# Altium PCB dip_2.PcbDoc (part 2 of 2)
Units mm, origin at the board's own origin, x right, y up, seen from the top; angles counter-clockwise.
Board outline 62.5 x 72.5 mm, 2 copper layers (Top Layer, Bottom Layer); 36 components, 64 nets, 215 pads, 49 vias.
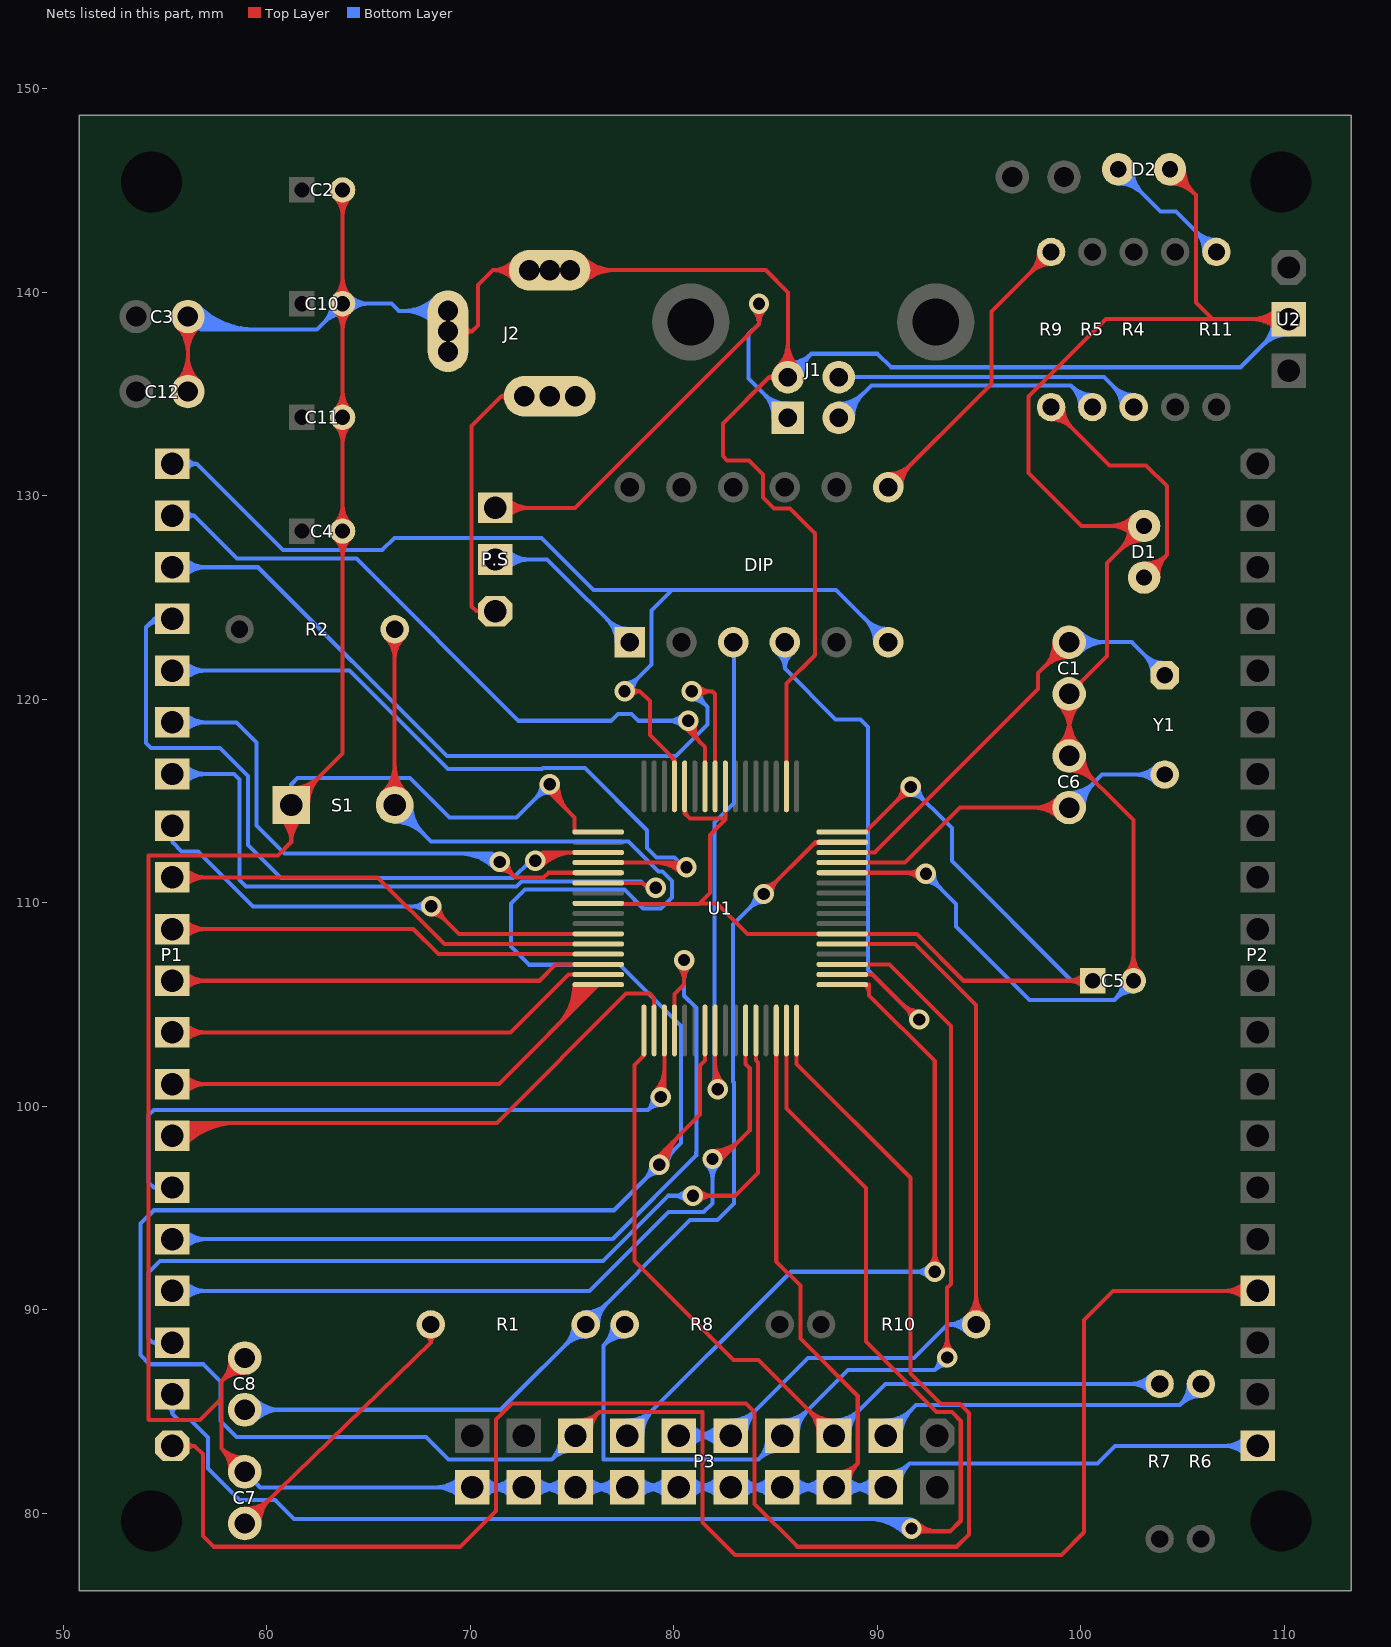
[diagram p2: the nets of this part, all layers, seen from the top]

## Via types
v1: diameter 1, hole 0.6, Top Layer to Bottom Layer, 49 vias

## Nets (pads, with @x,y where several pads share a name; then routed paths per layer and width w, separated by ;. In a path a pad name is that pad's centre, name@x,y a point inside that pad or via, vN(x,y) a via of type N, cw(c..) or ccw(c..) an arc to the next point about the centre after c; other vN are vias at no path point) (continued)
GND: C1.2 C2.2 C3.1 C4.2 C5.2 C6.2 C7.2 C8.2 C10.2 C11.2 C12.1 D1.2 D2.2 J1.4 J2.2 J2.2A J2.2B J2.3 J2.3A J2.3B P2.20 P3.4 P3.6 P3.8 P3.10 P3.12 P3.14 P3.16 P3.18 P3.20 S1.1 U1.2 U1.17 U1.46 U1.60 U2.2 | length 627.8
  Top Layer w0.2: C12.1@55.621,135.641 ccw(c54.384,136.878) 56.134,136.878 ccw(c57.884,136.878) C12.1@56.647,135.641 ; C3.1@55.621,138.298 cw(c54.384,137.061) 56.134,137.061 cw(c57.884,137.061) C3.1@56.647,138.298 ; C12.1@55.763,135.499 ccw(c54.867,136.395) 56.134,136.395 ccw(c57.401,136.395) C12.1@56.505,135.499 ; C3.1@55.763,138.44 cw(c54.867,137.544) 56.134,137.544 cw(c57.401,137.544) C3.1@56.505,138.44 ; C12.1@56.134,135.128 C3.1@56.134,138.811 ; C7.2@58.204,82.084 ccw(c56.767,82.167) 57.785,83.185 ; C8.2@58.204,87.588 cw(c56.767,87.505) 57.785,86.487 ; C7.2@58.404,82.072 ccw(c57.363,82.133) 58.1,82.87 ccw(c58.837,83.607) C7.2@58.898,82.566 ; C8.2@58.404,87.6 cw(c57.363,87.539) 58.1,86.802 cw(c58.837,86.065) C8.2@58.898,87.106 ; C7.2@58.886,82.766 cw(c58.803,84.203) 57.785,83.185 ; C8.2@58.886,86.906 ccw(c58.803,85.469) 57.785,86.487 ; C7.2@58.928,82.042 57.785,83.185 ; C8.2@58.928,87.63 57.785,86.487 ; S1.1@60.668,114.19 cw(c59.6,112.979) 61.214,112.979 ; S1.1@60.8,114.339 cw(c59.991,113.423) 61.214,113.423 cw(c62.437,113.423) S1.1@61.628,114.339 ; S1.1@60.933,114.489 cw(c60.382,113.866) 61.214,113.866 cw(c62.046,113.866) S1.1@61.495,114.489 ; S1.1@61.214,115.233 ccw(c61.214,116.259) 61.94,115.534 ccw(c62.665,114.808) S1.1@61.639,114.808 ; S1.1@61.214,115.433 ccw(c61.214,116.942) 62.281,115.875 ccw(c63.348,114.808) S1.1@61.839,114.808 ; S1.1@61.214,115.633 ccw(c61.214,117.625) 62.622,116.216 ccw(c64.031,114.808) S1.1@62.039,114.808 ; S1.1@61.76,114.19 ccw(c62.828,112.979) 61.214,112.979 ; C4.2@63.367,127.899 cw(c62.471,127.003) 63.738,127.003 cw(c65.005,127.003) C4.2@64.109,127.899 ; C4.2@63.367,128.641 ccw(c62.471,129.537) 63.738,129.537 ccw(c65.005,129.537) C4.2@64.109,128.641 ; C11.2@63.367,133.487 cw(c62.471,132.591) 63.738,132.591 cw(c65.005,132.591) C11.2@64.109,133.487 ; C11.2@63.367,134.229 ccw(c62.471,135.125) 63.738,135.125 ccw(c65.005,135.125) C11.2@64.109,134.229 ; C10.2@63.367,139.075 cw(c62.471,138.179) 63.738,138.179 cw(c65.005,138.179) C10.2@64.109,139.075 ; C10.2@63.367,139.817 ccw(c62.471,140.713) 63.738,140.713 ccw(c65.005,140.713) C10.2@64.109,139.817 ; C2.2@63.367,144.663 cw(c62.471,143.767) 63.738,143.767 cw(c65.005,143.767) C2.2@64.109,144.663 ; C4.2@63.508,128.04 cw(c62.953,127.485) 63.738,127.485 cw(c64.523,127.485) C4.2@63.968,128.04 ; C4.2@63.508,128.5 ccw(c62.953,129.055) 63.738,129.055 ccw(c64.523,129.055) C4.2@63.968,128.5 ; C11.2@63.508,133.628 cw(c62.953,133.073) 63.738,133.073 cw(c64.523,133.073) C11.2@63.968,133.628 ; C11.2@63.508,134.088 ccw(c62.953,134.643) 63.738,134.643 ccw(c64.523,134.643) C11.2@63.968,134.088 ; C10.2@63.508,139.216 cw(c62.953,138.661) 63.738,138.661 cw(c64.523,138.661) C10.2@63.968,139.216 ; C10.2@63.508,139.676 ccw(c62.953,140.231) 63.738,140.231 ccw(c64.523,140.231) C10.2@63.968,139.676 ; C2.2@63.508,144.804 cw(c62.953,144.249) 63.738,144.249 cw(c64.523,144.249) C2.2@63.968,144.804 ; C2.2@63.738,145.034 C10.2@63.738,139.446 C11.2@63.738,133.858 C4.2@63.738,128.27 63.738,117.332 S1.1@61.214,114.808 61.214,112.979 ; J2.3@68.65,137.684 ccw(c68.47,138.09) J2.3@68.914,138.09 ; J2.3@68.65,138.496 cw(c68.47,138.09) J2.3@68.914,138.09 ; J2.3B@68.914,137.09 J2.3@68.914,138.09 ; J2.3A@68.914,139.09 J2.3@68.914,138.09 ; J2.3@69.178,137.684 cw(c69.358,138.09) J2.3@68.914,138.09 ; J2.3@69.178,138.496 ccw(c69.358,138.09) J2.3@68.914,138.09 ; J2.3@69.78,137.845 cw(c70.104,137.753) 70.104,138.09 ; J2.3@69.78,138.335 ccw(c70.104,138.427) 70.104,138.09 ; J2.2@72.193,140.552 ccw(c71.12,139.752) 71.12,141.09 ; J2.2@72.193,141.628 cw(c71.12,142.428) 71.12,141.09 ; J2.2@72.353,140.672 ccw(c71.519,140.049) 71.519,141.09 ccw(c71.519,142.131) J2.2@72.353,141.508 ; J2.2@72.454,140.63 ccw(c71.345,139.521) 71.345,141.09 ccw(c71.345,142.659) J2.2@72.454,141.55 ; J2.2@72.596,140.772 ccw(c71.828,140.004) 71.828,141.09 ccw(c71.828,142.176) J2.2@72.596,141.408 ; J2.2@73.508,140.826 cw(c73.914,140.646) J2.2@73.914,141.09 ; J2.2@73.508,141.354 ccw(c73.914,141.534) J2.2@73.914,141.09 ; v1@74.114,115.824 ccw(c75.578,115.824) 74.543,114.789 ; 74.201,115.13 cw(c74.895,115.824) v1(73.914,115.824) 73.914,115.418 75.133,114.198 75.133,113.478 U1.17@76.3,113.478 ; v1@74.314,115.824 ccw(c76.261,115.824) 74.884,114.447 ; J2.2@74.32,140.826 ccw(c73.914,140.646) J2.2@73.914,141.09 ; J2.2@74.32,141.354 cw(c73.914,141.534) J2.2@73.914,141.09 ; J2.2@75.232,140.772 cw(c76,140.004) 76,141.09 cw(c76,142.176) J2.2@75.232,141.408 ; J2.2@75.268,140.736 cw(c76.121,139.883) 76.121,141.09 cw(c76.121,142.297) J2.2@75.268,141.444 ; J2.2@75.374,140.63 cw(c76.483,139.521) 76.483,141.09 cw(c76.483,142.659) J2.2@75.374,141.55 ; J2.2@75.409,140.595 cw(c76.604,139.4) 76.604,141.09 cw(c76.604,142.78) J2.2@75.409,141.585 ; J2.2@75.55,140.454 cw(c77.087,138.917) 77.087,141.09 cw(c77.087,143.263) J2.2@75.55,141.726 ; J1.4@84.942,135.651 ccw(c84.704,135.587) 84.704,135.834 ; J1.4@84.942,136.017 cw(c84.704,136.081) 84.704,135.834 ; U1.46@85.046,103.732 85.046,92.373 86.233,91.186 86.233,88.595 89.052,85.776 89.052,82.448 ; J1.4@85.123,136.329 ccw(c83.928,137.524) 85.618,137.524 ccw(c87.308,137.524) J1.4@86.113,136.329 ; J1.4@85.264,136.188 ccw(c84.411,137.041) 85.618,137.041 ccw(c86.825,137.041) J1.4@85.972,136.188 ; U1.2@85.546,115.724 85.546,120.769 86.944,122.167 86.944,128.161 85.727,129.379 84.938,129.379 84.404,129.912 84.404,131.051 83.712,131.744 82.632,131.744 82.423,131.953 82.423,133.553 84.704,135.834 ; P3.6@87.884,81.28 89.052,82.448 ; P3.6@87.921,81.829 ccw(c87.991,82.886) 88.741,82.137 ccw(c89.49,81.387) P3.6@88.433,81.317 ; P3.6@87.934,82.028 ccw(c88.031,83.47) 89.052,82.448 ; U1.60@88.292,111.478 92.352,111.478 v1(92.4,111.43) ; P3.6@88.632,81.33 cw(c90.074,81.427) 89.052,82.448 ; 91.318,111.478 cw(c91.318,110.348) v1@92.117,111.147 ; 91.55,111.478 ccw(c91.55,112.279) v1@92.117,111.713 ; 91.8,111.478 cw(c91.8,110.831) v1@92.258,111.288 ; C6.2@98.928,117.734 ccw(c97.691,118.971) 99.441,118.971 ccw(c101.191,118.971) C6.2@99.954,117.734 ; C1.2@98.928,119.756 cw(c97.691,118.519) 99.441,118.519 cw(c101.191,118.519) C1.2@99.954,119.756 ; C6.2@99.07,117.592 ccw(c98.174,118.488) 99.441,118.488 ccw(c100.708,118.488) C6.2@99.812,117.592 ; C1.2@99.07,119.898 cw(c98.174,119.002) 99.441,119.002 cw(c100.708,119.002) C1.2@99.812,119.898 ; C6.2@99.441,116.496 cw(c99.441,114.746) 100.679,115.983 cw(c101.916,117.221) C6.2@100.166,117.221 ; C6.2@99.441,116.696 cw(c99.441,115.429) 100.337,116.325 cw(c101.233,117.221) C6.2@99.966,117.221 ; C5.2@102.229,106.543 ccw(c101.333,107.439) 102.6,107.439 ccw(c103.867,107.439) C5.2@102.971,106.543 ; C5.2@102.37,106.402 ccw(c101.815,106.957) 102.6,106.957 ccw(c103.385,106.957) C5.2@102.83,106.402 ; D1.2@102.424,128.524 cw(c100.734,128.524) 101.929,127.329 cw(c103.124,126.134) D1.2@103.124,127.824 ; C5.2@102.6,106.172 102.6,114.062 C6.2@99.441,117.221 C1.2@99.441,120.269 101.295,122.123 101.295,126.695 D1.2@103.124,128.524 100.051,128.524 97.453,131.122 97.453,134.887 101.25,138.684 106.477,138.684 ; D1.2@102.624,128.524 cw(c101.417,128.524) 102.27,127.67 cw(c103.124,126.817) D1.2@103.124,128.024 ; D1.2@102.629,128.029 ccw(c101.434,126.834) 101.434,128.524 ccw(c101.434,130.214) D1.2@102.629,129.019 ; D1.2@102.77,128.17 ccw(c101.917,127.317) 101.917,128.524 ccw(c101.917,129.731) D1.2@102.77,128.878 ; D2.2@104.394,145.35 cw(c104.394,143.66) 105.589,144.855 cw(c106.784,146.05) D2.2@105.094,146.05 ; D2.2@104.394,145.55 cw(c104.394,144.343) 105.248,145.196 cw(c106.101,146.05) D2.2@104.894,146.05 ; D2.2@104.394,146.05 105.664,144.78 105.664,139.497 106.477,138.684 ; 57.785,83.185 57.785,85.649 ; 57.785,85.649 57.785,86.487 ; 57.785,85.649 56.718,84.582 54.229,84.582 54.204,84.607 54.204,112.319 60.554,112.319 61.214,112.979 ; 57.785,85.649 57.785,86.487 ; J2.3@68.914,138.09 70.104,138.09 ; 70.104,138.09 70.383,138.369 70.383,140.353 71.12,141.09 ; 71.12,141.09 J2.2A@72.914,141.09 J2.2@73.914,141.09 ; J2.2@73.914,141.09 J2.2B@74.914,141.09 84.531,141.09 85.618,140.003 J1.4@85.618,135.834 84.704,135.834 ; 106.477,138.684 U2.2@110.236,138.684 106.477,138.684 ; 108.425,138.684 ccw(c108.425,140.495) 109.706,139.214 cw(c108.425,140.495) 108.425,138.684 ; 108.425,138.684 cw(c108.425,136.873) 109.706,138.154 ccw(c108.425,136.873) 108.425,138.684 ; 108.908,138.684 ccw(c108.908,140.012) 109.847,139.073 cw(c108.908,140.012) 108.908,138.684 ; 108.908,138.684 cw(c108.908,137.356) 109.847,138.295 ccw(c108.908,137.356) 108.908,138.684
  Bottom Layer w0.2: C3.1@55.94,138.617 ccw(c57.003,139.68) 57.003,138.176 ; C3.1@56.081,138.758 ccw(c57.486,140.163) 57.486,138.176 ; C3.1@56.134,138.811 56.769,138.176 62.468,138.176 C10.2@63.738,139.446 66.142,139.446 66.498,139.09 J2.3A@68.914,139.09 ; C3.1@56.222,138.899 ccw(c57.969,140.646) 57.969,138.176 ; C3.1@56.364,139.041 ccw(c58.452,141.129) 58.452,138.176 ; C3.1@56.505,139.182 ccw(c58.934,141.611) 58.934,138.176 ; C3.1@56.647,139.324 ccw(c59.417,142.094) 59.417,138.176 ; C7.2@58.928,82.042 59.69,81.28 P3.20@70.104,81.28 P3.18@72.644,81.28 P3.16@75.184,81.28 P3.14@77.724,81.28 P3.12@80.264,81.28 P3.10@82.804,81.28 P3.8@85.344,81.28 P3.6@87.884,81.28 P3.4@90.424,81.28 91.592,82.448 ; S1.1@61.214,114.808 61.214,115.824 61.519,116.129 67.056,116.129 68.986,114.198 72.288,114.198 v1(73.914,115.824) ; C10.2@63.213,139.446 cw(c61.946,139.446) 62.842,138.55 cw(c63.738,137.654) C10.2@63.738,138.921 ; C10.2@63.413,139.446 cw(c62.628,139.446) 63.183,138.891 cw(c63.738,138.336) C10.2@63.738,139.121 ; C10.2@63.968,139.216 cw(c64.523,138.661) 64.523,139.446 cw(c64.523,140.231) C10.2@63.968,139.676 ; C10.2@64.109,139.075 cw(c65.005,138.179) 65.005,139.446 cw(c65.005,140.713) C10.2@64.109,139.817 ; J2.3@68.278,138.454 ccw(c66.741,136.917) 66.741,139.09 ccw(c66.741,141.263) J2.3@68.278,139.726 ; J2.3@68.419,138.595 ccw(c67.224,137.4) 67.224,139.09 ccw(c67.224,140.78) J2.3@68.419,139.585 ; J2.3@68.454,138.63 ccw(c67.345,137.521) 67.345,139.09 ccw(c67.345,140.659) J2.3@68.454,139.55 ; J2.3@68.56,138.736 ccw(c67.707,137.883) 67.707,139.09 ccw(c67.707,140.297) J2.3@68.56,139.444 ; J2.3@68.596,138.772 ccw(c67.828,138.004) 67.828,139.09 ccw(c67.828,140.176) J2.3@68.596,139.408 ; P3.20@69.574,80.75 ccw(c68.293,79.469) 68.293,81.28 ccw(c68.293,83.091) P3.20@69.574,81.81 ; P3.20@69.715,80.891 ccw(c68.776,79.952) 68.776,81.28 ccw(c68.776,82.608) P3.20@69.715,81.669 ; P3.20@70.493,80.891 cw(c71.432,79.952) 71.432,81.28 cw(c71.432,82.608) P3.20@70.493,81.669 ; P3.20@70.634,80.75 cw(c71.915,79.469) 71.915,81.28 cw(c71.915,83.091) P3.20@70.634,81.81 ; P3.18@72.114,80.75 ccw(c70.833,79.469) 70.833,81.28 ccw(c70.833,83.091) P3.18@72.114,81.81 ; P3.18@72.255,80.891 ccw(c71.316,79.952) 71.316,81.28 ccw(c71.316,82.608) P3.18@72.255,81.669 ; J2.2A@72.914,141.09 J2.2@73.914,141.09 ; P3.18@73.033,80.891 cw(c73.972,79.952) 73.972,81.28 cw(c73.972,82.608) P3.18@73.033,81.669 ; P3.18@73.174,80.75 cw(c74.455,79.469) 74.455,81.28 cw(c74.455,83.091) P3.18@73.174,81.81 ; J2.2@73.508,140.826 cw(c73.914,140.646) J2.2@73.914,141.09 ; J2.2@73.508,141.354 ccw(c73.914,141.534) J2.2@73.914,141.09 ; v1@73.514,115.824 cw(c72.548,115.824) 73.231,115.141 cw(c73.914,114.458) v1@73.914,115.424 ; J2.2@74.32,140.826 ccw(c73.914,140.646) J2.2@73.914,141.09 ; J2.2@74.32,141.354 cw(c73.914,141.534) J2.2@73.914,141.09 ; P3.16@74.654,80.75 ccw(c73.373,79.469) 73.373,81.28 ccw(c73.373,83.091) P3.16@74.654,81.81 ; P3.16@74.795,80.891 ccw(c73.856,79.952) 73.856,81.28 ccw(c73.856,82.608) P3.16@74.795,81.669 ; J2.2B@74.914,141.09 J2.2@73.914,141.09 ; P3.16@75.573,80.891 cw(c76.512,79.952) 76.512,81.28 cw(c76.512,82.608) P3.16@75.573,81.669 ; P3.16@75.714,80.75 cw(c76.995,79.469) 76.995,81.28 cw(c76.995,83.091) P3.16@75.714,81.81 ; P3.14@77.194,80.75 ccw(c75.913,79.469) 75.913,81.28 ccw(c75.913,83.091) P3.14@77.194,81.81 ; P3.14@77.335,80.891 ccw(c76.396,79.952) 76.396,81.28 ccw(c76.396,82.608) P3.14@77.335,81.669 ; P3.14@78.113,80.891 cw(c79.052,79.952) 79.052,81.28 cw(c79.052,82.608) P3.14@78.113,81.669 ; P3.14@78.254,80.75 cw(c79.535,79.469) 79.535,81.28 cw(c79.535,83.091) P3.14@78.254,81.81 ; P3.12@79.734,80.75 ccw(c78.453,79.469) 78.453,81.28 ccw(c78.453,83.091) P3.12@79.734,81.81 ; P3.12@79.875,80.891 ccw(c78.936,79.952) 78.936,81.28 ccw(c78.936,82.608) P3.12@79.875,81.669 ; P3.12@80.653,80.891 cw(c81.592,79.952) 81.592,81.28 cw(c81.592,82.608) P3.12@80.653,81.669 ; P3.12@80.794,80.75 cw(c82.075,79.469) 82.075,81.28 cw(c82.075,83.091) P3.12@80.794,81.81 ; P3.10@82.274,80.75 ccw(c80.993,79.469) 80.993,81.28 ccw(c80.993,83.091) P3.10@82.274,81.81 ; P3.10@82.415,80.891 ccw(c81.476,79.952) 81.476,81.28 ccw(c81.476,82.608) P3.10@82.415,81.669 ; P3.10@83.193,80.891 cw(c84.132,79.952) 84.132,81.28 cw(c84.132,82.608) P3.10@83.193,81.669 ; P3.10@83.334,80.75 cw(c84.615,79.469) 84.615,81.28 cw(c84.615,83.091) P3.10@83.334,81.81 ; P3.8@84.814,80.75 ccw(c83.533,79.469) 83.533,81.28 ccw(c83.533,83.091) P3.8@84.814,81.81 ; P3.8@84.955,80.891 ccw(c84.016,79.952) 84.016,81.28 ccw(c84.016,82.608) P3.8@84.955,81.669 ; J1.4@85.618,135.834 86.766,136.982 ; J1.4@85.632,136.334 ccw(c85.664,137.428) 86.438,136.654 ccw(c87.212,135.88) J1.4@86.118,135.848 ; J1.4@85.638,136.534 ccw(c85.682,138.066) 86.766,136.982 ; P3.8@85.733,80.891 cw(c86.672,79.952) 86.672,81.28 cw(c86.672,82.608) P3.8@85.733,81.669 ; P3.8@85.874,80.75 cw(c87.155,79.469) 87.155,81.28 cw(c87.155,83.091) P3.8@85.874,81.81 ; J1.4@86.318,135.854 cw(c87.85,135.898) 86.766,136.982 ; P3.6@87.354,80.75 ccw(c86.073,79.469) 86.073,81.28 ccw(c86.073,83.091) P3.6@87.354,81.81 ; P3.6@87.495,80.891 ccw(c86.556,79.952) 86.556,81.28 ccw(c86.556,82.608) P3.6@87.495,81.669 ; P3.6@88.273,80.891 cw(c89.212,79.952) 89.212,81.28 cw(c89.212,82.608) P3.6@88.273,81.669 ; P3.6@88.414,80.75 cw(c89.695,79.469) 89.695,81.28 cw(c89.695,83.091) P3.6@88.414,81.81 ; P3.4@89.894,80.75 ccw(c88.613,79.469) 88.613,81.28 ccw(c88.613,83.091) P3.4@89.894,81.81 ; P3.4@90.035,80.891 ccw(c89.096,79.952) 89.096,81.28 ccw(c89.096,82.608) P3.4@90.035,81.669 ; P3.4@90.461,81.829 ccw(c90.531,82.886) 91.281,82.137 ccw(c92.03,81.387) P3.4@90.973,81.317 ; P3.4@90.474,82.028 ccw(c90.571,83.47) 91.592,82.448 ; P3.4@91.172,81.33 cw(c92.614,81.427) 91.592,82.448 ; v1@92.4,111.03 cw(c92.4,110.064) 93.083,110.747 cw(c93.765,111.43) v1@92.8,111.43 ; v1(92.4,111.43) 93.889,109.941 93.889,108.829 97.485,105.232 101.66,105.232 C5.2@102.6,106.172 ; C5.2@102.075,106.172 cw(c100.808,106.172) 101.704,105.276 cw(c102.6,104.38) C5.2@102.6,105.647 ; C5.2@102.275,106.172 cw(c101.49,106.172) 102.045,105.617 cw(c102.6,105.062) C5.2@102.6,105.847 ; P2.20@108.152,82.852 ccw(c107.043,81.743) 107.043,83.312 ccw(c107.043,84.881) P2.20@108.152,83.772 ; P2.20@108.294,82.994 ccw(c107.526,82.226) 107.526,83.312 ccw(c107.526,84.398) P2.20@108.294,83.63 ; P2.20@108.712,83.312 101.702,83.312 100.838,82.448 91.592,82.448 ; U2.2@109.486,138.684 cw(c107.675,138.684) 108.956,137.404 cw(c110.236,136.123) U2.2@110.236,137.934 ; U2.2@109.686,138.684 cw(c108.358,138.684) 109.297,137.745 cw(c110.236,136.806) U2.2@110.236,138.134 ; U2.2@110.236,138.684 107.874,136.322 90.678,136.322 90.018,136.982 86.766,136.982
JTAGSEL: DIP.4 U1.50 | length 33.9
  Top Layer w0.2: U1.50@88.292,106.478 89.788,106.478 91.999,104.267 v1(92.075,104.267) ; 91.262,105.004 ccw(c92.075,105.817) v1@92.075,104.667 ; 91.446,104.82 cw(c90.893,104.267) v1@91.675,104.267 ; 91.603,104.662 ccw(c92.075,105.134) v1@92.075,104.467
  Bottom Layer w0.2: DIP.4@85.082,122.288 cw(c84.505,121.514) 85.471,121.514 ; DIP.4@85.202,122.448 cw(c84.802,121.912) 85.471,121.912 cw(c86.14,121.912) DIP.4@85.74,122.448 ; DIP.4@85.471,122.809 85.471,121.514 ; DIP.4@85.86,122.288 ccw(c86.437,121.514) 85.471,121.514 ; 91.262,105.004 ccw(c92.075,105.817) v1@92.075,104.667 ; 91.446,104.82 cw(c90.893,104.267) v1@91.675,104.267 ; 91.603,104.662 ccw(c92.075,105.134) v1@92.075,104.467 ; v1(92.075,104.267) 91.999,104.267 89.56,106.705 89.56,118.65 89.193,119.018 87.967,119.018 85.471,121.514
LEDSWCH: DIP.6 P1.20 U1.13 | length 68.8
  Top Layer w0.2: v1(77.597,120.396) 78.359,120.396 ; v1@77.926,120.169 cw(c78.359,119.87) 78.359,120.396 ; v1@77.926,120.623 ccw(c78.359,120.922) 78.359,120.396 ; 79.884,117.205 cw(c79.552,116.874) U1.13@80.021,116.874 ; U1.13@80.046,115.724 80.046,117.043 78.842,118.248 78.842,119.913 78.359,120.396
  Bottom Layer w0.2: P1.20@55.372,131.572 56.586,131.572 ; P1.20@55.864,131.351 cw(c56.243,131.136) 56.243,131.572 cw(c56.243,132.008) P1.20@55.864,131.793 ; P1.20@56.038,131.252 cw(c56.586,130.943) 56.586,131.572 ; P1.20@56.038,131.892 ccw(c56.586,132.201) 56.586,131.572 ; v1(77.597,120.396) 78.918,121.717 78.918,124.358 79.934,125.374 ; v1@77.597,120.796 ccw(c77.597,121.762) 78.28,121.079 ccw(c78.963,120.396) v1@77.997,120.396 ; DIP.6@89.901,122.809 ccw(c88.332,122.809) 89.441,123.919 ccw(c90.551,125.028) DIP.6@90.551,123.459 ; DIP.6@90.101,122.809 ccw(c89.015,122.809) 89.783,123.577 ccw(c90.551,124.345) DIP.6@90.551,123.259 ; DIP.6@90.551,122.809 87.986,125.374 ; 56.586,131.572 60.813,127.345 65.684,127.345 66.279,127.94 73.508,127.94 76.073,125.374 79.934,125.374 ; 79.934,125.374 87.986,125.374 ; 79.934,125.374 87.986,125.374
LEDSWCH1: DIP.7 R9.2 | length 22.8
  Top Layer w0.2: DIP.7@90.551,130.429 95.624,135.502 95.624,139.058 R9.2@98.552,141.986 ; DIP.7@90.551,130.879 ccw(c90.551,131.965) 91.319,131.197 ccw(c92.087,130.429) DIP.7@91.001,130.429 ; DIP.7@90.551,131.079 ccw(c90.551,132.648) 91.661,131.539 ccw(c92.77,130.429) DIP.7@91.201,130.429 ; R9.2@97.952,141.986 cw(c96.503,141.986) 97.528,140.962 cw(c98.552,139.937) R9.2@98.552,141.386 ; R9.2@98.152,141.986 cw(c97.186,141.986) 97.869,141.303 cw(c98.552,140.62) R9.2@98.552,141.586
NetC7_1: C7.1 R1.2 | length 19.2
  Top Layer w0.2: C7.1@58.928,79.502 68.072,88.392 ; C7.1@58.935,80.027 ccw(c58.953,81.294) 59.837,80.386 ccw(c60.72,79.477) C7.1@59.453,79.495 ; C7.1@58.938,80.227 ccw(c58.963,81.977) 60.183,80.722 ccw(c61.403,79.467) C7.1@59.653,79.492 ; R1.2@67.848,88.725 cw(c67.713,88.392) 68.072,88.392 ; R1.2@68.072,89.281 68.072,88.392 ; R1.2@68.296,88.725 ccw(c68.431,88.392) 68.072,88.392
NetD1_1: D1.1 R9.1 | length 20.2
  Top Layer w0.2: R9.1@98.552,133.766 cw(c98.552,132.317) 99.576,133.342 cw(c100.601,134.366) R9.1@99.152,134.366 ; R9.1@98.552,133.966 cw(c98.552,133) 99.235,133.683 cw(c99.918,134.366) R9.1@98.952,134.366 ; R9.1@98.552,134.366 101.422,131.496 103.226,131.496 104.242,130.48 104.242,127.102 ; D1.1@103.124,125.984 104.242,127.102 ; D1.1@103.148,126.483 ccw(c103.198,127.507) 103.922,126.782 ccw(c104.647,126.058) D1.1@103.623,126.008 ; D1.1@103.158,126.683 ccw(c103.227,128.116) 104.242,127.102 ; D1.1@103.823,126.018 cw(c105.256,126.087) 104.242,127.102
NetD2_1: D2.1 R11.2 | length 14.9
  Bottom Layer w0.2: D2.1@101.854,145.35 cw(c101.854,143.66) 103.049,144.855 cw(c104.244,146.05) D2.1@102.554,146.05 ; D2.1@101.854,145.55 cw(c101.854,144.343) 102.708,145.196 cw(c103.561,146.05) D2.1@102.354,146.05 ; D2.1@101.854,146.05 103.937,143.967 104.699,143.967 R11.2@106.68,141.986 ; R11.2@106.08,141.986 ccw(c104.631,141.986) 105.656,143.01 ccw(c106.68,144.035) R11.2@106.68,142.586 ; R11.2@106.28,141.986 ccw(c105.314,141.986) 105.997,142.669 ccw(c106.68,143.352) R11.2@106.68,142.386
NetDIPs_1: DIP.1 P.S.2 | length 16.6
  Bottom Layer w0.2: P.S.2@71.247,126.873 73.787,126.873 DIP.1@77.851,122.809 ; P.S.2@71.665,126.555 cw(c72.433,125.787) 72.433,126.873 cw(c72.433,127.959) P.S.2@71.665,127.191 ; P.S.2@71.807,126.413 cw(c72.916,125.304) 72.916,126.873 cw(c72.916,128.442) P.S.2@71.807,127.333 ; DIP.1@77.201,122.809 ccw(c75.632,122.809) 76.741,123.919 ccw(c77.851,125.028) DIP.1@77.851,123.459 ; DIP.1@77.401,122.809 ccw(c76.315,122.809) 77.083,123.577 ccw(c77.851,124.345) DIP.1@77.851,123.259
NetJ1_1: J1.1 P.S.3 | length 36.1
  Top Layer w0.2: P.S.3@71.247,129.413 75.159,129.413 84.201,138.455 v1(84.201,139.446) ; P.S.3@71.665,129.095 cw(c72.433,128.327) 72.433,129.413 cw(c72.433,130.499) P.S.3@71.665,129.731 ; P.S.3@71.807,128.953 cw(c72.916,127.844) 72.916,129.413 cw(c72.916,130.982) P.S.3@71.807,129.873 ; v1@83.918,139.163 cw(c83.235,138.48) 84.201,138.48 cw(c85.167,138.48) v1@84.484,139.163
  Bottom Layer w0.2: v1@83.918,139.163 cw(c83.235,138.48) 84.201,138.48 cw(c85.167,138.48) v1@84.484,139.163 ; v1(84.201,139.446) 84.201,138.455 83.693,137.947 83.693,135.759 J1.1@85.618,133.834 ; J1.1@84.918,133.834 ccw(c83.228,133.834) 84.423,135.029 ccw(c85.618,136.224) J1.1@85.618,134.534 ; J1.1@85.118,133.834 ccw(c83.911,133.834) 84.764,134.688 ccw(c85.618,135.541) J1.1@85.618,134.334
NetJ1_2: J1.2 R5.1 | length 21.9
  Bottom Layer w0.2: J1.2@88.118,133.834 89.718,135.434 99.516,135.434 R5.1@100.584,134.366 ; J1.2@88.118,134.334 ccw(c88.118,135.541) 88.972,134.688 ccw(c89.825,133.834) J1.2@88.618,133.834 ; J1.2@88.118,134.534 ccw(c88.118,136.224) 89.313,135.029 ccw(c90.508,133.834) J1.2@88.818,133.834 ; R5.1@99.984,134.366 ccw(c98.535,134.366) 99.56,135.39 ccw(c100.584,136.415) R5.1@100.584,134.966 ; R5.1@100.184,134.366 ccw(c99.218,134.366) 99.901,135.049 ccw(c100.584,135.732) R5.1@100.584,134.766
NetJ1_3: J1.3 R4.1 | length 18.9
  Bottom Layer w0.2: J1.3@88.118,135.834 101.148,135.834 R4.1@102.616,134.366 ; R4.1@102.016,134.366 ccw(c100.567,134.366) 101.592,135.39 ccw(c102.616,136.415) R4.1@102.616,134.966 ; R4.1@102.216,134.366 ccw(c101.25,134.366) 101.933,135.049 ccw(c102.616,135.732) R4.1@102.616,134.766
NetJ2_1: J2.1 J2.1A J2.1B P.S.1 | length 28.7
  Top Layer w0.2: P.S.1@71.247,124.333 70.307,124.333 70.079,124.562 70.079,133.442 71.526,134.89 ; J2.1@71.788,134.683 ccw(c71.526,134.621) 71.526,134.89 ; J2.1@71.788,135.097 cw(c71.526,135.159) 71.526,134.89 ; J2.1@72.104,134.56 ccw(c71.526,134.22) 71.526,134.89 ; J2.1@72.104,135.22 cw(c71.526,135.56) 71.526,134.89 ; J2.1@72.276,134.662 ccw(c71.876,134.426) 71.876,134.89 ccw(c71.876,135.354) J2.1@72.276,135.118 ; J2.1@73.032,134.632 cw(c73.529,134.283) 73.529,134.89 cw(c73.529,135.497) J2.1@73.032,135.148 ; J2.1@73.196,134.517 cw(c73.914,134.013) J2.1@73.914,134.89 ; J2.1@73.196,135.263 ccw(c73.914,135.767) J2.1@73.914,134.89 ; 71.526,134.89 J2.1A@72.664,134.89 J2.1@73.914,134.89
  Bottom Layer w0.2: J2.1A@72.664,134.89 J2.1@73.914,134.89 ; J2.1@73.032,134.632 cw(c73.529,134.283) 73.529,134.89 cw(c73.529,135.497) J2.1@73.032,135.148 ; J2.1@73.196,134.517 cw(c73.914,134.013) J2.1@73.914,134.89 ; J2.1@73.196,135.263 ccw(c73.914,135.767) J2.1@73.914,134.89 ; J2.1@74.632,134.517 ccw(c73.914,134.013) J2.1@73.914,134.89 ; J2.1@74.632,135.263 cw(c73.914,135.767) J2.1@73.914,134.89 ; J2.1@74.796,134.632 ccw(c74.299,134.283) 74.299,134.89 ccw(c74.299,135.497) J2.1@74.796,135.148 ; J2.1B@75.164,134.89 J2.1@73.914,134.89
NetP1_1: P1.1 U1.48 | length 84.7
  Top Layer w0.2: P1.1@55.372,83.312 56.464,83.312 ; P1.1@56.068,83.052 cw(c56.464,82.88) 56.464,83.312 ; P1.1@56.068,83.572 ccw(c56.464,83.744) 56.464,83.312 ; U1.48@86.046,103.732 86.046,102.083 91.637,96.492 91.637,86.881 93.148,85.37 94.082,85.37 94.514,84.938 94.514,78.955 93.918,78.359 86.081,78.359 83.972,80.467 83.972,84.988 83.566,85.395 72.06,85.395 71.272,84.607 71.272,80.112 69.52,78.359 57.404,78.359 56.871,78.892 56.871,82.906 56.464,83.312
NetP1_2: P1.2 U1.47 | length 81.1
  Top Layer w0.2: U1.47@85.546,103.732 85.546,99.898 89.459,95.985 89.459,88.443 92.932,84.97 93.675,84.97 94.114,84.531 94.114,79.636 93.599,79.121 91.821,79.121 v1(91.694,79.248) ; v1@91.835,79.389 ccw(c92.483,80.037) 92.483,79.121 ; v1@91.977,78.965 cw(c92.353,78.589) 92.353,79.121 ; v1@91.977,79.531 ccw(c92.966,80.52) 92.966,79.121
  Bottom Layer w0.2: P1.2@55.128,85.25 cw(c54.98,84.887) 55.372,84.887 ; P1.2@55.372,85.852 55.372,84.887 ; P1.2@55.616,85.25 ccw(c55.764,84.887) 55.372,84.887 ; 89.563,79.731 cw(c89.563,77.117) v1@91.411,78.965 ; 90.046,79.731 cw(c90.046,77.6) v1@91.553,79.107 ; 90.529,79.731 cw(c90.529,78.083) v1(91.694,79.248) 91.694,79.629 91.592,79.731 61.341,79.731 60.427,80.645 58.674,80.645 57.125,82.194 57.125,83.718 56.261,84.582 55.677,84.582 55.372,84.887 ; 91.012,79.731 cw(c91.012,78.566) v1@91.835,79.389 ; 91.495,79.731 cw(c91.495,79.049) v1@91.977,79.531
NetP1_3: P1.3 U1.44 | length 47.2
  Top Layer w0.2: v1(80.95,95.606) 83.026,95.606 84.144,96.723 84.144,102.159 84.046,102.257 U1.44@84.046,103.732 ; v1@81.233,95.323 cw(c81.915,94.64) 81.915,95.606 cw(c81.915,96.571) v1@81.233,95.888
  Bottom Layer w0.2: P1.3@54.648,88.211 ccw(c54.407,88.141) 54.407,88.392 ; P1.3@54.648,88.573 cw(c54.407,88.643) 54.407,88.392 ; P1.3@55.372,88.392 54.407,88.392 ; v1@80.667,95.323 ccw(c79.984,94.64) 79.984,95.606 ccw(c79.984,96.571) v1@80.667,95.888 ; v1(80.95,95.606) 79.731,95.606 76.53,92.405 54.762,92.405 54.204,91.846 54.204,88.595 54.407,88.392
NetP1_4: P1.4 U1.43 | length 47.2
  Top Layer w0.2: v1@81.915,97.609 ccw(c81.915,99.134) 82.994,98.056 ; v1@81.915,97.809 ccw(c81.915,99.817) 83.335,98.397 ; 82.652,97.714 cw(c81.915,98.451) v1(81.915,97.409) 82.347,97.409 83.744,98.806 83.744,101.886 83.546,102.084 U1.43@83.546,103.732
  Bottom Layer w0.2: P1.4@55.372,90.932 75.87,90.932 79.743,94.806 81.483,94.806 81.915,95.237 v1(81.915,97.409) ; P1.4@55.79,90.614 cw(c56.558,89.846) 56.558,90.932 cw(c56.558,92.018) P1.4@55.79,91.25 ; P1.4@55.932,90.472 cw(c57.041,89.363) 57.041,90.932 cw(c57.041,92.501) P1.4@55.932,91.392 ; v1@81.632,97.126 cw(c80.949,96.443) 81.915,96.443 cw(c82.881,96.443) v1@82.198,97.126
NetP1_5: P1.5 U1.36 | length 48.2
  Top Layer w0.2: U1.36@80.046,103.732 80.046,105.522 80.518,105.994 v1(80.518,107.188) ; v1@80.235,106.905 cw(c79.552,106.222) 80.518,106.222 cw(c81.484,106.222) v1@80.801,106.905
  Bottom Layer w0.2: P1.5@55.372,93.472 77.013,93.472 81.115,97.574 81.115,97.74 81.128,97.753 81.128,104.826 80.518,105.435 v1(80.518,107.188) ; P1.5@55.79,93.154 cw(c56.558,92.386) 56.558,93.472 cw(c56.558,94.558) P1.5@55.79,93.79 ; P1.5@55.932,93.012 cw(c57.041,91.903) 57.041,93.472 cw(c57.041,95.041) P1.5@55.932,93.932 ; v1@80.235,106.905 cw(c79.552,106.222) 80.518,106.222 cw(c81.484,106.222) v1@80.801,106.905
NetP1_6: P1.6 U1.35 | length 37.2
  Top Layer w0.2: v1@79.092,100.74 ccw(c77.997,101.835) 79.546,101.835 ; v1@79.234,100.598 ccw(c78.479,101.353) 79.546,101.353 ; v1(79.375,100.457) 79.546,100.628 U1.35@79.546,103.732 ; 79.546,101.01 ccw(c79.928,101.01) v1@79.658,100.74
  Bottom Layer w0.2: P1.6@55.372,96.012 54.458,96.012 54.204,96.266 54.204,99.568 54.458,99.822 78.74,99.822 ; v1@78.976,100.436 cw(c78.169,100.393) 78.74,99.822 ; v1@79.354,100.058 ccw(c79.311,99.251) 78.74,99.822 ; v1(79.375,100.457) 78.74,99.822
NetP1_7: P1.7 U1.34 | length 40.2
  Top Layer w0.2: P1.7@55.225,98.799 cw(c56.16,97.864) P1.7@56.16,99.187 ; P1.7@55.366,98.658 cw(c56.643,97.381) 56.643,99.187 ; P1.7@55.372,98.552 56.007,99.187 71.323,99.187 77.673,105.537 78.842,105.537 79.046,105.333 U1.34@79.046,103.732 ; P1.7@55.507,98.517 cw(c57.126,96.898) 57.126,99.187 ; P1.7@55.649,98.375 cw(c57.609,96.415) 57.609,99.187 ; P1.7@55.79,98.234 cw(c58.091,95.933) 58.091,99.187 ; P1.7@55.932,98.092 cw(c58.574,95.45) 58.574,99.187
NetP1_8: P1.8 U1.32 | length 34.8
  Top Layer w0.2: P1.8@55.372,101.092 71.414,101.092 U1.32@76.3,105.978 ; P1.8@55.79,100.774 cw(c56.558,100.006) 56.558,101.092 cw(c56.558,102.178) P1.8@55.79,101.41 ; P1.8@55.932,100.632 cw(c57.041,99.523) 57.041,101.092 cw(c57.041,102.661) P1.8@55.932,101.552 ; 74.294,103.972 ccw(c72.288,105.978) U1.32@75.125,105.978 ; 74.636,104.314 ccw(c72.971,105.978) U1.32@75.325,105.978 ; 74.977,104.655 ccw(c73.654,105.978) U1.32@75.525,105.978 ; 75.318,104.996 ccw(c74.337,105.978) U1.32@75.725,105.978 ; 75.66,105.338 ccw(c75.02,105.978) U1.32@75.925,105.978 ; 76.001,105.679 ccw(c75.703,105.978) U1.32@76.125,105.978
NetP1_9: P1.9 U1.31 | length 26.3
  Top Layer w0.2: P1.9@55.372,103.632 71.984,103.632 74.83,106.478 U1.31@76.3,106.478 ; P1.9@55.79,103.314 cw(c56.558,102.546) 56.558,103.632 cw(c56.558,104.718) P1.9@55.79,103.95 ; P1.9@55.932,103.172 cw(c57.041,102.063) 57.041,103.632 cw(c57.041,105.201) P1.9@55.932,104.092
NetP1_10: P1.10 U1.30 | length 25.4
  Top Layer w0.2: P1.10@55.372,106.172 73.402,106.172 74.208,106.978 U1.30@76.3,106.978 ; P1.10@55.79,105.854 cw(c56.558,105.086) 56.558,106.172 cw(c56.558,107.258) P1.10@55.79,106.49 ; P1.10@55.932,105.712 cw(c57.041,104.603) 57.041,106.172 cw(c57.041,107.741) P1.10@55.932,106.632
NetP1_11: P1.11 U1.29 | length 25.6
  Top Layer w0.2: P1.11@55.372,108.712 67.209,108.712 68.443,107.478 U1.29@76.3,107.478 ; P1.11@55.79,108.394 cw(c56.558,107.626) 56.558,108.712 cw(c56.558,109.798) P1.11@55.79,109.03 ; P1.11@55.932,108.252 cw(c57.041,107.143) 57.041,108.712 cw(c57.041,110.281) P1.11@55.932,109.172
NetP1_12: P1.12 U1.28 | length 26.5
  Top Layer w0.2: P1.12@55.372,111.252 65.462,111.252 68.736,107.978 U1.28@76.3,107.978 ; P1.12@55.79,110.934 cw(c56.558,110.166) 56.558,111.252 cw(c56.558,112.338) P1.12@55.79,111.57 ; P1.12@55.932,110.792 cw(c57.041,109.683) 57.041,111.252 cw(c57.041,112.821) P1.12@55.932,111.712
NetP1_13: P1.13 U1.27 | length 26.6
  Top Layer w0.2: v1@68.097,109.43 cw(c68.097,108.464) 68.78,109.147 cw(c69.463,109.83) v1@68.497,109.83 ; v1(68.097,109.83) 69.449,108.478 U1.27@76.3,108.478
  Bottom Layer w0.2: P1.13@55.372,113.792 55.372,112.979 55.829,112.522 56.642,112.522 59.334,109.83 v1(68.097,109.83) ; v1@67.815,109.547 ccw(c67.132,108.864) 67.132,109.83 ccw(c67.132,110.795) v1@67.815,110.112
NetP1_14: P1.14 U1.22 | length 36.2
  Top Layer w0.2: U1.22@76.3,110.978 78.486,110.978 78.72,110.744 v1(79.121,110.744)
  Bottom Layer w0.2: P1.14@55.372,116.332 58.395,116.332 58.674,116.053 58.674,111.125 58.985,110.814 72.287,110.814 72.528,111.055 78.409,111.055 78.72,110.744 v1(79.121,110.744) ; P1.14@55.79,116.014 cw(c56.558,115.246) 56.558,116.332 cw(c56.558,117.418) P1.14@55.79,116.65 ; P1.14@55.932,115.872 cw(c57.041,114.763) 57.041,116.332 cw(c57.041,117.901) P1.14@55.932,116.792
NetP1_15: P1.15 U1.21 | length 37.4
  Top Layer w0.2: v1@71.457,111.614 cw(c71.457,110.648) 72.14,111.331 cw(c72.822,112.014) v1@71.857,112.014 ; v1(71.457,112.014) 72.224,111.247 73.615,111.247 73.847,111.478 U1.21@76.3,111.478
  Bottom Layer w0.2: P1.15@55.372,118.872 58.522,118.872 59.512,117.881 59.512,113.792 60.884,112.42 71.05,112.42 v1(71.457,112.014) ccw(c70.476,111.033) 70.476,112.42 ; P1.15@55.79,118.554 cw(c56.558,117.786) 56.558,118.872 cw(c56.558,119.958) P1.15@55.79,119.19 ; P1.15@55.932,118.412 cw(c57.041,117.303) 57.041,118.872 cw(c57.041,120.441) P1.15@55.932,119.332 ; 69.51,112.42 cw(c69.51,110.067) v1@71.174,111.731 ; 69.993,112.42 cw(c69.993,110.55) v1@71.315,111.873 ; 70.958,112.42 cw(c70.958,111.516) v1@71.598,112.155
NetP1_16: P1.16 U1.20 | length 41.4
  Top Layer w0.2: U1.20@76.3,111.978 80.292,111.978 80.518,111.752 v1(80.637,111.752) ccw(c80.09,111.205) 80.09,111.978 ; 79.125,111.978 cw(c79.125,110.24) v1@80.354,111.469 ; 79.607,111.978 cw(c79.607,110.722) v1@80.495,111.61
  Bottom Layer w0.2: P1.16@55.372,121.412 64.084,121.412 68.91,116.586 73.545,116.586 73.583,116.624 75.646,116.624 78.702,113.568 78.702,112.699 79.171,112.23 80.04,112.23 80.518,111.752 v1(80.637,111.752) ; P1.16@55.79,121.094 cw(c56.558,120.326) 56.558,121.412 cw(c56.558,122.498) P1.16@55.79,121.73 ; P1.16@55.932,120.952 cw(c57.041,119.843) 57.041,121.412 cw(c57.041,122.981) P1.16@55.932,121.872
NetP1_17: P1.17 U1.19 | length 43
  Top Layer w0.2: v1@73.061,112.206 cw(c73.718,111.55) 73.718,112.478 ; v1@73.344,111.923 cw(c74.683,110.584) 74.683,112.478 ; v1@73.486,111.782 cw(c75.166,110.102) U1.19@75.166,112.478 ; 74.2,112.478 ccw(c74.2,111.067) v1(73.203,112.065) 73.616,112.478 U1.19@76.3,112.478
  Bottom Layer w0.2: 54.078,123.547 cw(c54.746,122.879) P1.17@55.162,123.727 ; 54.276,123.745 cw(c54.876,123.144) P1.17@55.25,123.907 ; 54.474,123.943 cw(c55.007,123.41) P1.17@55.338,124.087 ; P1.17@55.372,123.952 54.483,123.952 54.077,123.546 54.077,117.856 54.331,117.602 57.709,117.602 59.08,116.23 59.08,112.852 60.719,111.214 72.121,111.214 72.972,112.065 v1(73.203,112.065)
NetP1_18: P1.18 U1.9 | length 45.7
  Top Layer w0.2: v1(80.899,120.396) 81.915,120.396 82.046,120.265 U1.9@82.046,115.724 ; v1@81.182,120.113 cw(c81.865,119.43) 81.865,120.396 cw(c81.865,121.362) v1@81.182,120.679
  Bottom Layer w0.2: P1.18@55.372,126.492 59.588,126.492 68.859,117.221 80.125,117.221 81.661,118.757 81.661,119.634 v1(80.899,120.396) ; P1.18@55.79,126.174 cw(c56.558,125.406) 56.558,126.492 cw(c56.558,127.578) P1.18@55.79,126.81 ; P1.18@55.932,126.032 cw(c57.041,124.923) 57.041,126.492 cw(c57.041,128.061) P1.18@55.932,126.952 ; v1@80.899,119.996 cw(c80.899,119.03) 81.582,119.713 cw(c82.265,120.396) v1@81.299,120.396
NetP1_19: P1.19 U1.10 | length 38.5
  Top Layer w0.2: 80.86,118.334 cw(c81.277,118.751) v1(80.721,118.948) 80.543,118.77 80.543,118.65 81.546,117.648 U1.10@81.546,115.724 ; v1@80.91,118.881 ccw(c81.608,118.634) 81.084,118.11 ; v1@81.098,118.814 ccw(c81.939,118.516) 81.308,117.886
  Bottom Layer w0.2: P1.19@55.372,129.032 56.439,129.032 ; P1.19@56.074,128.787 cw(c56.439,128.638) 56.439,129.032 ; P1.19@56.074,129.277 ccw(c56.439,129.426) 56.439,129.032 ; v1@80.438,118.665 ccw(c79.756,117.983) 79.756,118.948 ccw(c79.756,119.914) v1@80.438,119.231 ; v1(80.721,118.948) 78.271,118.948 77.928,119.291 77.266,119.291 76.923,118.948 72.39,118.948 64.414,126.924 58.547,126.924 56.439,129.032
NetP3_3: P3.3 R6.2 | length 25.3
  Bottom Layer w0.2: P3.3@90.424,83.82 91.923,85.319 104.877,85.319 R6.2@105.918,86.36 ; P3.3@90.424,84.37 ccw(c90.424,85.698) 91.363,84.759 ccw(c92.302,83.82) P3.3@90.974,83.82 ; P3.3@90.424,84.57 ccw(c90.424,86.381) 91.704,85.1 ccw(c92.985,83.82) P3.3@91.174,83.82 ; R6.2@105.318,86.36 cw(c103.869,86.36) 104.894,85.336 cw(c105.918,84.311) R6.2@105.918,85.76 ; R6.2@105.518,86.36 cw(c104.552,86.36) 105.235,85.677 cw(c105.918,84.994) R6.2@105.918,85.96
NRST: P2.17 P3.15 R2.1 S1.2 U1.39 | length 212.4
  Top Layer w0.2: S1.2@65.711,115.391 ccw(c64.302,116.8) 66.294,116.8 ccw(c68.286,116.8) S1.2@66.877,115.391 ; S1.2@65.852,115.25 ccw(c64.785,116.317) 66.294,116.317 ccw(c67.803,116.317) S1.2@66.736,115.25 ; R2.1@65.87,123.02 cw(c64.845,121.995) 66.294,121.995 cw(c67.743,121.995) R2.1@66.718,123.02 ; S1.2@65.993,115.109 ccw(c65.268,115.834) 66.294,115.834 ccw(c67.32,115.834) S1.2@66.595,115.109 ; R2.1@66.011,123.161 cw(c65.328,122.478) 66.294,122.478 cw(c67.26,122.478) R2.1@66.577,123.161 ; S1.2@66.294,114.808 R2.1@66.294,123.444 ; P3.15@75.184,83.82 76.352,84.988 ; P3.15@75.221,84.369 ccw(c75.291,85.426) 76.041,84.677 ccw(c76.79,83.927) P3.15@75.733,83.857 ; P3.15@75.234,84.568 ccw(c75.331,86.01) 76.352,84.988 ; P3.15@75.932,83.87 cw(c77.374,83.967) 76.352,84.988 ; v1@79.499,97.13 cw(c81.085,97.13) 79.964,98.252 ; 79.622,97.91 ccw(c80.403,97.13) v1(79.299,97.13) 79.299,97.587 81.305,99.593 81.305,102.006 81.546,102.247 U1.39@81.546,103.732 ; v1@79.699,97.13 cw(c81.768,97.13) 80.305,98.593 ; P2.17@108.152,90.472 ccw(c107.043,89.363) 107.043,90.932 ccw(c107.043,92.501) P2.17@108.152,91.392 ; P2.17@108.294,90.614 ccw(c107.526,89.846) 107.526,90.932 ccw(c107.526,92.018) P2.17@108.294,91.25 ; P2.17@108.712,90.932 101.6,90.932 100.178,89.51 100.178,79.07 99.066,77.959 83.026,77.959 81.432,79.553 81.432,84.988 76.352,84.988
  Bottom Layer w0.2: S1.2@66.294,113.983 cw(c66.294,111.991) 67.702,113.4 cw(c69.111,114.808) S1.2@67.119,114.808 ; S1.2@66.294,114.183 cw(c66.294,112.674) 67.361,113.741 cw(c68.428,114.808) S1.2@66.919,114.808 ; S1.2@66.294,114.383 cw(c66.294,113.357) 67.02,114.082 cw(c67.745,114.808) S1.2@66.719,114.808 ; S1.2@66.294,114.808 68.082,113.02 77.784,113.02 79.261,111.544 79.452,111.544 79.921,111.075 79.921,110.27 79.379,109.728 78.511,109.728 77.584,110.655 72.694,110.655 72.009,109.97 72.009,107.851 72.901,106.959 77.343,106.959 80.366,103.937 80.366,98.196 v1(79.299,97.13) ; P3.15@74.436,83.77 cw(c72.994,83.673) 74.016,82.652 ; P3.15@74.635,83.783 cw(c73.578,83.713) 74.327,82.963 cw(c75.077,82.214) P3.15@75.147,83.271 ; P3.15@75.134,83.072 ccw(c75.037,81.63) 74.016,82.652 ; P3.15@75.184,83.82 74.016,82.652 ; v1@79.299,97.53 ccw(c79.299,98.495) 79.982,97.812 ccw(c80.664,97.13) v1@79.699,97.13 ; 74.016,82.652 68.936,82.652 67.843,83.744 58.522,83.744 57.734,84.531 57.734,86.487 56.896,87.325 54.254,87.325 53.797,87.782 53.797,94.234 54.458,94.894 77.064,94.894 ; 77.064,94.894 v1(79.299,97.13) ; 77.064,94.894 v1(79.299,97.13) ; 78.616,96.447 ccw(c77.933,97.13) 78.899,97.13 cw(c77.933,97.13) 78.616,96.447 ; 78.616,96.447 cw(c79.299,95.764) 79.299,96.73 ccw(c79.299,95.764) 78.616,96.447
PLLRC: C8.1 R1.1 U1.63 | length 65
  Top Layer w0.2: v1(84.43,110.438) 86.97,112.978 U1.63@88.292,112.978 ; v1@84.43,110.838 ccw(c84.43,111.804) 85.112,111.121 ccw(c85.795,110.438) v1@84.83,110.438 ; 86.805,112.813 cw(c87.142,112.476) U1.63@87.142,112.953 ; 86.883,112.892 cw(c87.061,112.714) U1.63@87.135,112.954
  Bottom Layer w0.2: C8.1@58.928,85.09 71.501,85.09 R1.1@75.692,89.281 80.817,94.406 82.15,94.406 82.969,95.225 82.969,101.169 82.931,101.207 82.931,108.939 v1(84.43,110.438) ; C8.1@59.299,84.719 cw(c60.195,83.823) 60.195,85.09 cw(c60.195,86.357) C8.1@59.299,85.461 ; C8.1@59.441,84.577 cw(c60.678,83.34) 60.678,85.09 cw(c60.678,86.84) C8.1@59.441,85.603 ; R1.1@75.092,89.281 cw(c73.643,89.281) 74.668,88.257 cw(c75.692,87.232) R1.1@75.692,88.681 ; R1.1@75.292,89.281 cw(c74.326,89.281) 75.009,88.598 cw(c75.692,87.915) R1.1@75.692,88.881 ; R1.1@75.692,89.681 ccw(c75.692,90.647) 76.375,89.964 ccw(c77.058,89.281) R1.1@76.092,89.281 ; R1.1@75.692,89.881 ccw(c75.692,91.33) 76.716,90.305 ccw(c77.741,89.281) R1.1@76.292,89.281 ; v1@84.03,110.438 cw(c83.064,110.438) 83.747,109.755 cw(c84.43,109.072) v1@84.43,110.038
TCK: P3.9 P3.11 R10.2 U1.53 | length 62.6
  Top Layer w0.2: U1.53@88.292,107.978 91.876,107.978 94.869,104.985 R10.2@94.869,89.281 ; R10.2@94.445,89.705 ccw(c93.42,90.73) 94.869,90.73 ccw(c96.318,90.73) R10.2@95.293,89.705 ; R10.2@94.586,89.564 ccw(c93.903,90.247) 94.869,90.247 ccw(c95.835,90.247) R10.2@95.152,89.564
  Bottom Layer w0.2: P3.11@80.264,83.82 P3.9@82.804,83.82 86.614,87.63 91.808,87.63 93.459,89.281 ; P3.11@80.653,83.431 cw(c81.592,82.492) 81.592,83.82 cw(c81.592,85.148) P3.11@80.653,84.209 ; P3.11@80.794,83.29 cw(c82.075,82.009) 82.075,83.82 cw(c82.075,85.631) P3.11@80.794,84.35 ; P3.9@82.274,83.29 ccw(c80.993,82.009) 80.993,83.82 ccw(c80.993,85.631) P3.9@82.274,84.35 ; P3.9@82.415,83.431 ccw(c81.476,82.492) 81.476,83.82 ccw(c81.476,85.148) P3.9@82.415,84.209 ; P3.9@82.804,84.37 ccw(c82.804,85.698) 83.743,84.759 ccw(c84.682,83.82) P3.9@83.354,83.82 ; P3.9@82.804,84.57 ccw(c82.804,86.381) 84.084,85.1 ccw(c85.365,83.82) P3.9@83.554,83.82 ; R10.2@94.437,88.865 ccw(c93.459,87.924) 93.459,89.281 ; R10.2@94.437,89.697 cw(c93.459,90.638) 93.459,89.281 ; R10.2@94.581,89.004 ccw(c93.929,88.376) 93.929,89.281 ccw(c93.929,90.186) R10.2@94.581,89.558 ; R10.2@94.869,89.281 93.459,89.281
TDI: P3.5 R7.2 U1.33 | length 55.8
  Top Layer w0.2: 78.446,102.402 ccw(c78.266,102.582) U1.33@78.521,102.582 ; U1.33@78.546,103.732 78.546,102.502 78.078,102.033 78.078,92.407 82.956,87.528 84.176,87.528 P3.5@87.884,83.82 ; P3.5@87.134,83.82 ccw(c85.323,83.82) 86.604,85.1 ccw(c87.884,86.381) P3.5@87.884,84.57 ; P3.5@87.334,83.82 ccw(c86.006,83.82) 86.945,84.759 ccw(c87.884,85.698) P3.5@87.884,84.37
  Bottom Layer w0.2: P3.5@87.884,83.82 90.424,86.36 R7.2@103.886,86.36 ; P3.5@87.884,84.37 ccw(c87.884,85.698) 88.823,84.759 ccw(c89.762,83.82) P3.5@88.434,83.82 ; P3.5@87.884,84.57 ccw(c87.884,86.381) 89.164,85.1 ccw(c90.445,83.82) P3.5@88.634,83.82 ; R7.2@103.462,85.936 ccw(c102.437,84.911) 102.437,86.36 ccw(c102.437,87.809) R7.2@103.462,86.784 ; R7.2@103.603,86.077 ccw(c102.92,85.394) 102.92,86.36 ccw(c102.92,87.326) R7.2@103.603,86.643
TDO: P3.13 U1.49 | length 43.7
  Top Layer w0.2: U1.49@88.292,105.978 89.615,105.978 89.615,105.457 92.837,102.235 v1(92.837,91.872) ; U1.49@89.424,105.96 cw(c88.965,105.501) 89.615,105.501 ; v1@92.554,92.155 ccw(c91.871,92.837) 92.837,92.837 ccw(c93.803,92.837) v1@93.12,92.155
  Bottom Layer w0.2: P3.13@77.724,83.82 85.776,91.872 v1(92.837,91.872) ; P3.13@77.724,84.37 ccw(c77.724,85.698) 78.663,84.759 ccw(c79.602,83.82) P3.13@78.274,83.82 ; P3.13@77.724,84.57 ccw(c77.724,86.381) 79.004,85.1 ccw(c80.285,83.82) P3.13@78.474,83.82 ; v1@92.554,91.589 ccw(c91.871,90.906) 91.871,91.872 ccw(c91.871,92.837) v1@92.554,92.155
TMS: P3.7 R8.2 U1.51 | length 64.8
  Top Layer w0.2: U1.51@88.292,106.978 90.609,106.978 93.637,103.95 93.637,91.275 93.447,91.084 v1(93.447,87.655) ; v1@93.164,87.938 ccw(c92.481,88.621) 93.447,88.621 ccw(c94.412,88.621) v1@93.729,87.938
  Bottom Layer w0.2: R8.2@76.997,89.281 cw(c75.548,89.281) 76.573,88.257 cw(c77.597,87.232) R8.2@77.597,88.681 ; R8.2@77.197,89.281 cw(c76.231,89.281) 76.914,88.598 cw(c77.597,87.915) R8.2@77.597,88.881 ; R8.2@77.597,89.281 76.556,88.24 76.556,82.652 84.176,82.652 ; P3.7@84.596,83.77 cw(c83.154,83.673) 84.176,82.652 ; P3.7@84.795,83.783 cw(c83.738,83.713) 84.487,82.963 cw(c85.237,82.214) P3.7@85.307,83.271 ; P3.7@85.294,83.072 ccw(c85.197,81.63) 84.176,82.652 ; P3.7@85.344,84.37 ccw(c85.344,85.698) 86.283,84.759 ccw(c87.222,83.82) P3.7@85.894,83.82 ; P3.7@85.344,84.57 ccw(c85.344,86.381) 86.624,85.1 ccw(c87.905,83.82) P3.7@86.094,83.82 ; v1@93.048,87.622 cw(c92.322,87.561) 92.837,87.046 ; v1@93.413,87.257 ccw(c93.352,86.53) 92.837,87.046 ; v1(93.447,87.655) 92.837,87.046 ; 84.176,82.652 P3.7@85.344,83.82 88.57,87.046 92.837,87.046
TST: DIP.3 U1.40 | length 30
  Top Layer w0.2: v1@81.886,101.121 ccw(c81.5,101.507) 82.046,101.507 ; 82.046,101.618 ccw(c82.949,101.618) v1@82.31,100.979 ; 82.046,102.101 ccw(c83.432,102.101) v1@82.452,101.121 ; U1.40@82.046,103.732 82.046,100.961 v1(82.169,100.838)
  Bottom Layer w0.2: v1@81.886,101.121 ccw(c81.602,101.405) 82.004,101.405 ; 82.004,101.719 ccw(c83.05,101.719) v1@82.31,100.979 ; 82.004,102.202 ccw(c83.533,102.202) v1@82.452,101.121 ; v1(82.169,100.838) 82.004,101.003 82.004,113.944 82.963,114.903 82.963,122.777 DIP.3@82.931,122.809
VDDCORE: C5.1 U1.8 U1.12 U1.24 U1.54 U1.64 | length 69.5
  Top Layer w0.2: U1.12@80.546,115.724 80.546,114.402 80.8,114.148 82.537,114.148 82.546,114.156 ; U1.12@80.571,114.574 ccw(c81.048,114.574) 80.711,114.237 ; U1.64@88.292,113.478 89.433,113.478 v1(91.652,115.697) ; v1@91.252,115.697 cw(c90.287,115.697) 90.97,115.014 cw(c91.652,114.331) v1@91.652,115.297 ; C5.1@100.229,105.801 ccw(c99.333,104.905) 99.333,106.172 ccw(c99.333,107.439) C5.1@100.229,106.543 ; C5.1@100.37,105.942 ccw(c99.815,105.387) 99.815,106.172 ccw(c99.815,106.957) C5.1@100.37,106.402 ; C5.1@100.6,106.172 94.259,106.172 91.953,108.478 U1.54@88.292,108.478 83.63,108.478 82.13,109.978 81.28,109.978 ; U1.24@76.334,109.944 81.246,109.944 ; U1.24@76.334,109.944 U1.24@76.3,109.978 U1.24@76.334,109.944 ; U1.24@76.334,109.944 81.246,109.944 ; 81.246,109.944 81.28,109.978 ; 81.246,109.944 81.28,109.978 ; 81.28,109.978 81.788,110.486 81.788,113.344 82.546,114.102 82.546,114.156 ; 82.546,114.156 U1.8@82.546,115.724 82.546,114.156 ; U1.24@77.468,109.996 ccw(c77.592,110.12) 77.592,109.944 cw(c77.592,110.12) U1.24@77.468,109.996
  Bottom Layer w0.2: v1@91.652,115.297 cw(c91.652,114.331) 92.335,115.014 cw(c93.018,115.697) v1@92.052,115.697 ; v1(91.652,115.697) 93.675,113.674 93.675,112.065 99.568,106.172 ; C5.1@100.176,105.863 ccw(c99.568,105.42) 99.568,106.172 ; C5.1@100.176,106.481 cw(c99.568,106.924) 99.568,106.172 ; C5.1@100.337,105.981 ccw(c99.961,105.707) 99.961,106.172 ccw(c99.961,106.637) C5.1@100.337,106.363 ; C5.1@100.6,106.172 99.568,106.172
XIN: C1.1 U1.62 Y1.1 | length 34.5
  Top Layer w0.2: U1.62@88.292,112.478 89.887,112.478 97.916,120.507 97.916,121.284 C1.1@99.441,122.809 ; C1.1@98.716,122.809 cw(c96.966,122.809) 98.203,121.571 cw(c99.441,120.334) C1.1@99.441,122.084 ; C1.1@98.916,122.809 cw(c97.649,122.809) 98.545,121.913 cw(c99.441,121.017) C1.1@99.441,122.284
  Bottom Layer w0.2: C1.1@99.441,122.809 102.516,122.809 Y1.1@104.14,121.185 ; C1.1@99.812,122.438 cw(c100.708,121.542) 100.708,122.809 cw(c100.708,124.076) C1.1@99.812,123.18 ; C1.1@99.954,122.296 cw(c101.191,121.059) 101.191,122.809 cw(c101.191,124.559) C1.1@99.954,123.322 ; Y1.1@103.54,121.185 ccw(c102.091,121.185) 103.116,122.209 ccw(c104.14,123.234) Y1.1@104.14,121.785 ; Y1.1@103.74,121.185 ccw(c102.774,121.185) 103.457,121.868 ccw(c104.14,122.551) Y1.1@104.14,121.585
XOUT: C6.1 U1.61 Y1.2 | length 30.9
  Top Layer w0.2: U1.61@88.292,111.978 91.379,111.978 94.082,114.681 C6.1@99.441,114.681 ; C6.1@98.928,114.168 ccw(c97.691,112.931) 97.691,114.681 ccw(c97.691,116.431) C6.1@98.928,115.194 ; C6.1@99.07,114.31 ccw(c98.174,113.414) 98.174,114.681 ccw(c98.174,115.948) C6.1@99.07,115.052
  Bottom Layer w0.2: C6.1@99.441,114.681 101.065,116.305 Y1.2@104.14,116.305 ; C6.1@99.441,115.206 ccw(c99.441,116.473) 100.337,115.577 ccw(c101.233,114.681) C6.1@99.966,114.681 ; C6.1@99.441,115.406 ccw(c99.441,117.156) 100.679,115.919 ccw(c101.916,114.681) C6.1@100.166,114.681 ; Y1.2@103.716,115.881 ccw(c102.691,114.856) 102.691,116.305 ccw(c102.691,117.754) Y1.2@103.716,116.729 ; Y1.2@103.857,116.022 ccw(c103.174,115.339) 103.174,116.305 ccw(c103.174,117.271) Y1.2@103.857,116.588
pads on no net: J1.5 J1.6 P3.17 P3.19
copper on no net: | length 12.3
  Top Layer w0.254: 72.077,92.038 ccw(c71.319,95.385) 74.74,95.118 ccw(c74.538,95.2) 74.324,95.244
  Top Layer w0.5: 72.065,92.09 ccw(c70.739,94.742) 73.246,96.325 ccw(c72.916,96.08) 72.511,96.011 ; 73.015,98.414 cw(c73.211,98.386) 73.017,98.347

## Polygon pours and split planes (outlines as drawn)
GND on Top Layer "Top Overlay-No Net" (hatched 90Degree grid 0.508 track 0.203): 52.324,147.193 52.324,77.724 111.76,77.724 111.887,77.851 111.887,147.193
GND on Bottom Layer "Top Overlay-No Net" (hatched 90Degree grid 0.508 track 0.203): 52.324,147.193 52.324,77.724 111.76,77.724 111.76,147.193

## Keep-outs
Keep-Out Layer:
  rectangle: 107.569,77.47 112.014,81.661
  rectangle: 52.07,77.47 56.515,81.661
  rectangle: 52.07,143.256 56.515,147.447
  rectangle: 107.569,143.256 112.014,147.447
  lines w0.3: 52.1,77.5 52.1,147.4 112,147.4 112,77.5 52.1,77.5

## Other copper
Top Layer:
  text "AT91SAM7S" at 58.039,95.885 h1.52
  text "Iranvig" at 58.039,93.345 h1.52

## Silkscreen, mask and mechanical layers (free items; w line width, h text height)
Top Overlay:
  lines w0.254: 58.42,142.494 58.42,141.224 57.912,140.716 ; 57.912,140.716 58.293,140.716 57.912,141.097 57.912,140.716
  text "P" at 78.486,119.38 h1.52 r90
  text "E" at 81.026,119.38 h1.52 r90
  text "T" at 83.566,119.38 h1.52 r90
  text "J" at 86.106,119.38 h1.52 r90
  text "L" at 91.186,119.38 h1.52 r90
  text "AD" at 88.646,118.11 h1.52 r90
Drill Drawing:
  text ".LEGEND" at 118.38,81.28 h1.52
  text "Drill Drawing." at 118.38,78.74 h1.52

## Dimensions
52.1,77.5 to 52.1,147.4 on Mechanical 1
52.1,77.5 to 112,77.5 on Mechanical 1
